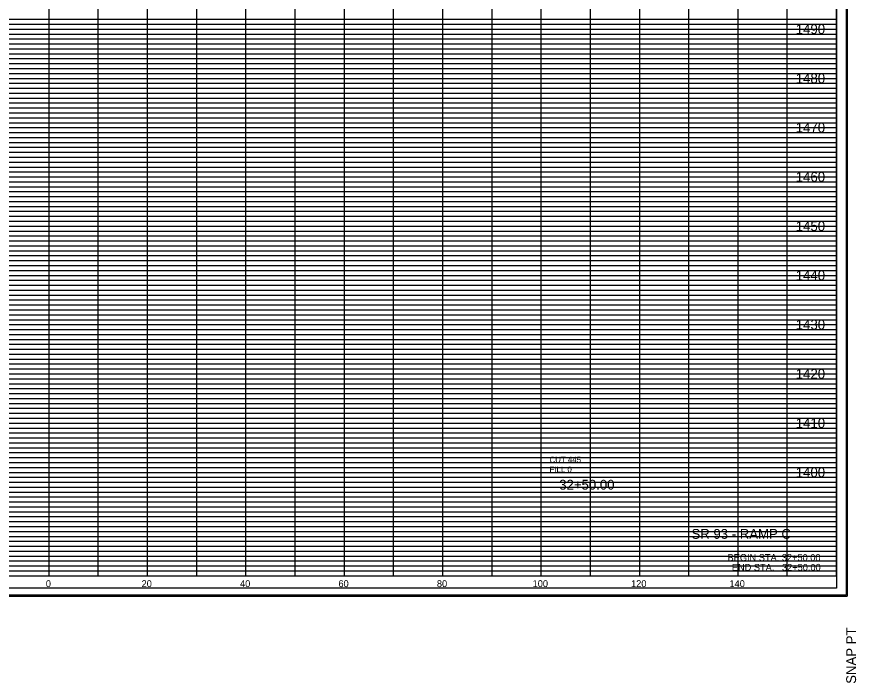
# Model space of a CAD drawing. Extents: x 980 to 2064, y 978 to 2267.
# Drawn here: x 1523.4 to 1694, y 978.2 to 1113.5 of the extents above; entities that cross this region are included whole.
import ezdxf

# ---------------------------------------------------------------- set-up
doc = ezdxf.new("R2010")
doc.units = 0
for name, color, linetype in [('Default', 7, 'Continuous'), ('DESIGN - SHEET - Corner Text', 7, 'Continuous'), ('DESIGN - SHEET - Light Grid', 7, 'Continuous'), ('DESIGN - SHEET - Linework', 7, 'Continuous'), ('DESIGN - SHEET - Plot Shape', 7, 'Continuous'), ('DESIGN - TYPICAL - Text', 7, 'Continuous')]:
    doc.layers.add(name, color=color, linetype=linetype)

# ---------------------------------------------------------------- blocks, each defined once
blk = doc.blocks.new('XSTSHT')
at = {"layer": 'DESIGN - SHEET - Light Grid'}
for p, q in [((8, 11.3), (16, 11.3)), ((16, 11.3), (24, 11.3)), ((24, 11.3), (32, 11.3)), ((8, 11.2), (16, 11.2)), ((8, 11.1), (16, 11.1)), ((16, 11.2), (24, 11.2)), ((16, 11.1), (24, 11.1)), ((24, 11.2), (32, 11.2)), ((24, 11.1), (32, 11.1)), ((8, 10.9), (16, 10.9)), ((8, 10.8), (16, 10.8)), ((16, 10.9), (24, 10.9)), ((16, 10.8), (24, 10.8)), ((24, 10.9), (32, 10.9)), ((24, 10.8), (32, 10.8)), ((8, 10.7), (16, 10.7)), ((8, 10.6), (16, 10.6)), ((16, 10.7), (24, 10.7)), ((16, 10.6), (24, 10.6)), ((24, 10.7), (32, 10.7)), ((24, 10.6), (32, 10.6)), ((8, 10.5), (16, 10.5)), ((16, 10.5), (24, 10.5)), ((24, 10.5), (32, 10.5)), ((8, 10.4), (16, 10.4)), ((8, 10.3), (16, 10.3)), ((16, 10.4), (24, 10.4)), ((16, 10.3), (24, 10.3)), ((24, 10.4), (32, 10.4)), ((24, 10.3), (32, 10.3)), ((8, 10.2), (16, 10.2)), ((8, 10.1), (16, 10.1)), ((16, 10.2), (24, 10.2)), ((16, 10.1), (24, 10.1)), ((24, 10.2), (32, 10.2)), ((24, 10.1), (32, 10.1)), ((8, 9.9), (16, 9.9)), ((16, 9.9), (24, 9.9)), ((24, 9.9), (32, 9.9)), ((8, 9.8), (16, 9.8)), ((16, 9.8), (24, 9.8)), ((24, 9.8), (32, 9.8)), ((8, 9.7), (16, 9.7)), ((8, 9.6), (16, 9.6)), ((16, 9.7), (24, 9.7)), ((16, 9.6), (24, 9.6)), ((24, 9.7), (32, 9.7)), ((24, 9.6), (32, 9.6)), ((8, 9.5), (16, 9.5)), ((8, 9.4), (16, 9.4)), ((16, 9.5), (24, 9.5)), ((16, 9.4), (24, 9.4)), ((24, 9.5), (32, 9.5)), ((24, 9.4), (32, 9.4)), ((8, 9.3), (16, 9.3)), ((16, 9.3), (24, 9.3)), ((24, 9.3), (32, 9.3)), ((8, 9.2), (16, 9.2)), ((8, 9.1), (16, 9.1)), ((16, 9.2), (24, 9.2)), ((16, 9.1), (24, 9.1)), ((24, 9.2), (32, 9.2)), ((24, 9.1), (32, 9.1)), ((8, 8.9), (16, 8.9)), ((16, 8.9), (24, 8.9)), ((24, 8.9), (32, 8.9)), ((8, 8.8), (16, 8.8)), ((8, 8.7), (16, 8.7)), ((16, 8.8), (24, 8.8)), ((16, 8.7), (24, 8.7)), ((24, 8.8), (32, 8.8)), ((24, 8.7), (32, 8.7)), ((8, 8.6), (16, 8.6)), ((16, 8.6), (24, 8.6)), ((24, 8.6), (32, 8.6)), ((8, 8.5), (16, 8.5)), ((8, 8.4), (16, 8.4)), ((16, 8.5), (24, 8.5)), ((16, 8.4), (24, 8.4)), ((24, 8.5), (32, 8.5)), ((24, 8.4), (32, 8.4)), ((8, 8.3), (16, 8.3)), ((8, 8.2), (16, 8.2)), ((16, 8.3), (24, 8.3)), ((16, 8.2), (24, 8.2)), ((24, 8.3), (32, 8.3)), ((24, 8.2), (32, 8.2)), ((8, 8.1), (16, 8.1)), ((16, 8.1), (24, 8.1)), ((24, 8.1), (32, 8.1)), ((8, 7.9), (16, 7.9)), ((16, 7.9), (24, 7.9)), ((24, 7.9), (32, 7.9)), ((8, 7.8), (16, 7.8)), ((8, 7.7), (16, 7.7)), ((16, 7.8), (24, 7.8)), ((16, 7.7), (24, 7.7)), ((24, 7.8), (32, 7.8)), ((24, 7.7), (32, 7.7)), ((8, 7.6), (16, 7.6)), ((16, 7.6), (24, 7.6)), ((24, 7.6), (32, 7.6)), ((8, 7.5), (16, 7.5)), ((8, 7.4), (16, 7.4)), ((16, 7.5), (24, 7.5)), ((16, 7.4), (24, 7.4)), ((24, 7.5), (32, 7.5)), ((24, 7.4), (32, 7.4)), ((8, 7.3), (16, 7.3)), ((8, 7.2), (16, 7.2)), ((16, 7.3), (24, 7.3)), ((16, 7.2), (24, 7.2)), ((24, 7.3), (32, 7.3)), ((24, 7.2), (32, 7.2)), ((8, 7.1), (16, 7.1)), ((16, 7.1), (24, 7.1)), ((24, 7.1), (32, 7.1)), ((8, 6.9), (16, 6.9)), ((16, 6.9), (24, 6.9)), ((24, 6.9), (32, 6.9)), ((8, 6.8), (16, 6.8)), ((8, 6.7), (16, 6.7)), ((16, 6.8), (24, 6.8)), ((16, 6.7), (24, 6.7)), ((24, 6.8), (32, 6.8)), ((24, 6.7), (32, 6.7)), ((8, 6.6), (16, 6.6)), ((8, 6.5), (16, 6.5)), ((16, 6.6), (24, 6.6)), ((16, 6.5), (24, 6.5)), ((24, 6.6), (32, 6.6)), ((24, 6.5), (32, 6.5)), ((8, 6.4), (16, 6.4)), ((16, 6.4), (24, 6.4)), ((24, 6.4), (32, 6.4)), ((8, 6.3), (16, 6.3)), ((8, 6.2), (16, 6.2)), ((16, 6.3), (24, 6.3)), ((16, 6.2), (24, 6.2)), ((24, 6.3), (32, 6.3)), ((24, 6.2), (32, 6.2)), ((8, 6.1), (16, 6.1)), ((16, 6.1), (24, 6.1)), ((24, 6.1), (32, 6.1)), ((8, 5.9), (16, 5.9)), ((8, 5.8), (16, 5.8)), ((16, 5.9), (24, 5.9)), ((16, 5.8), (24, 5.8)), ((24, 5.9), (32, 5.9)), ((24, 5.8), (32, 5.8)), ((8, 5.7), (16, 5.7)), ((16, 5.7), (24, 5.7)), ((24, 5.7), (32, 5.7)), ((8, 5.6), (16, 5.6)), ((8, 5.5), (16, 5.5)), ((16, 5.6), (24, 5.6)), ((16, 5.5), (24, 5.5)), ((24, 5.6), (32, 5.6)), ((24, 5.5), (32, 5.5)), ((8, 5.4), (16, 5.4)), ((8, 5.3), (16, 5.3)), ((16, 5.4), (24, 5.4)), ((16, 5.3), (24, 5.3)), ((24, 5.4), (32, 5.4)), ((24, 5.3), (32, 5.3)), ((8, 5.2), (16, 5.2)), ((16, 5.2), (24, 5.2)), ((24, 5.2), (32, 5.2)), ((8, 5.1), (16, 5.1)), ((16, 5.1), (24, 5.1)), ((24, 5.1), (32, 5.1)), ((8, 4.9), (16, 4.9)), ((8, 4.8), (16, 4.8)), ((16, 4.9), (24, 4.9)), ((16, 4.8), (24, 4.8)), ((24, 4.9), (32, 4.9)), ((24, 4.8), (32, 4.8)), ((8, 4.7), (16, 4.7)), ((16, 4.7), (24, 4.7)), ((24, 4.7), (32, 4.7)), ((8, 4.6), (16, 4.6)), ((8, 4.5), (16, 4.5)), ((16, 4.6), (24, 4.6)), ((16, 4.5), (24, 4.5)), ((24, 4.6), (32, 4.6)), ((24, 4.5), (32, 4.5)), ((8, 4.4), (16, 4.4)), ((8, 4.3), (16, 4.3)), ((16, 4.4), (24, 4.4)), ((16, 4.3), (24, 4.3)), ((24, 4.4), (32, 4.4)), ((24, 4.3), (32, 4.3)), ((8, 4.2), (16, 4.2)), ((8, 4.1), (16, 4.1)), ((16, 4.2), (24, 4.2)), ((16, 4.1), (24, 4.1)), ((24, 4.2), (32, 4.2)), ((24, 4.1), (32, 4.1)), ((8, 3.9), (16, 3.9)), ((8, 3.8), (16, 3.8)), ((16, 3.9), (24, 3.9)), ((16, 3.8), (24, 3.8)), ((24, 3.9), (32, 3.9)), ((24, 3.8), (32, 3.8)), ((8, 3.7), (16, 3.7)), ((8, 3.6), (16, 3.6)), ((16, 3.7), (24, 3.7)), ((16, 3.6), (24, 3.6)), ((24, 3.7), (32, 3.7)), ((24, 3.6), (32, 3.6)), ((8, 3.5), (16, 3.5)), ((16, 3.5), (24, 3.5)), ((24, 3.5), (32, 3.5)), ((8, 3.4), (16, 3.4)), ((8, 3.3), (16, 3.3)), ((16, 3.4), (24, 3.4)), ((16, 3.3), (24, 3.3)), ((24, 3.4), (32, 3.4)), ((24, 3.3), (32, 3.3)), ((8, 3.2), (16, 3.2)), ((8, 3.1), (16, 3.1)), ((16, 3.2), (24, 3.2)), ((16, 3.1), (24, 3.1)), ((24, 3.2), (32, 3.2)), ((24, 3.1), (32, 3.1)), ((8, 2.9), (16, 2.9)), ((16, 2.9), (24, 2.9)), ((24, 2.9), (32, 2.9)), ((8, 2.8), (16, 2.8)), ((16, 2.8), (24, 2.8)), ((24, 2.8), (32, 2.8)), ((8, 2.7), (16, 2.7)), ((8, 2.6), (16, 2.6)), ((16, 2.7), (24, 2.7)), ((16, 2.6), (24, 2.6)), ((24, 2.7), (32, 2.7)), ((24, 2.6), (32, 2.6)), ((8, 2.5), (16, 2.5)), ((8, 2.4), (16, 2.4)), ((16, 2.5), (24, 2.5)), ((16, 2.4), (24, 2.4)), ((24, 2.5), (32, 2.5)), ((24, 2.4), (32, 2.4)), ((8, 2.3), (16, 2.3)), ((16, 2.3), (24, 2.3)), ((24, 2.3), (32, 2.3)), ((8, 2.2), (16, 2.2)), ((8, 2.1), (16, 2.1)), ((16, 2.2), (24, 2.2)), ((16, 2.1), (24, 2.1)), ((24, 2.2), (32, 2.2)), ((24, 2.1), (32, 2.1)), ((8, 1.9), (16, 1.9)), ((16, 1.9), (24, 1.9)), ((24, 1.9), (32, 1.9)), ((8, 1.8), (16, 1.8)), ((16, 1.8), (24, 1.8)), ((24, 1.8), (32, 1.8)), ((8, 1.7), (16, 1.7)), ((8, 1.6), (16, 1.6)), ((16, 1.7), (24, 1.7)), ((16, 1.6), (24, 1.6)), ((24, 1.7), (32, 1.7)), ((24, 1.6), (32, 1.6)), ((8, 1.5), (16, 1.5)), ((8, 1.4), (16, 1.4)), ((16, 1.5), (24, 1.5)), ((16, 1.4), (24, 1.4)), ((24, 1.5), (32, 1.5)), ((24, 1.4), (32, 1.4)), ((8, 1.3), (16, 1.3)), ((8, 1.2), (16, 1.2)), ((16, 1.3), (24, 1.3)), ((16, 1.2), (24, 1.2)), ((24, 1.3), (32, 1.3)), ((24, 1.2), (32, 1.2)), ((8, 1.1), (16, 1.1)), ((16, 1.1), (24, 1.1)), ((24, 1.1), (32, 1.1)), ((8, 0.9), (16, 0.9)), ((16, 0.9), (24, 0.9)), ((24, 0.9), (32, 0.9)), ((8, 0.8), (16, 0.8)), ((8, 0.7), (16, 0.7)), ((16, 0.8), (24, 0.8)), ((16, 0.7), (24, 0.7)), ((24, 0.8), (32, 0.8)), ((24, 0.7), (32, 0.7)), ((8, 0.6), (16, 0.6)), ((16, 0.6), (24, 0.6)), ((24, 0.6), (32, 0.6)), ((8, 0.5), (16, 0.5)), ((8, 0.4), (16, 0.4)), ((16, 0.5), (24, 0.5)), ((16, 0.4), (24, 0.4)), ((24, 0.5), (32, 0.5)), ((24, 0.4), (32, 0.4)), ((8, 0.3), (16, 0.3)), ((8, 0.2), (16, 0.2)), ((16, 0.3), (24, 0.3)), ((16, 0.2), (24, 0.2)), ((24, 0.3), (32, 0.3)), ((24, 0.2), (32, 0.2)), ((8, 0.1), (16, 0.1)), ((16, 0.1), (24, 0.1)), ((24, 0.1), (32, 0.1))]:
    blk.add_line(p, q, dxfattribs=at)
at = {"layer": 'DESIGN - SHEET - Linework'}
for p, q in [((32.217, 21.414), (32.217, -0.414)), ((16, 0), (16, 21)), ((17, 0), (17, 21)), ((18, 0), (18, 21)), ((19, 0), (19, 21)), ((20, 0), (20, 21)), ((21, 0), (21, 21)), ((22, 0), (22, 21)), ((23, 0), (23, 21)), ((24, 0), (24, 21)), ((25, 0), (25, 21)), ((26, 0), (26, 21)), ((27, 0), (27, 21)), ((28, 0), (28, 20)), ((29, 0), (29, 20)), ((30, 0), (30, 20)), ((31, 0), (31, 20)), ((0, 11), (32, 11)), ((0, 10), (32, 10)), ((0, 9), (32, 9)), ((0, 8), (32, 8)), ((0, 7), (32, 7)), ((0, 6), (32, 6)), ((0, 5), (32, 5)), ((0, 4), (32, 4)), ((0, 3), (32, 3)), ((0, 2), (32, 2)), ((0, 1), (32, 1)), ((-1.823, -0.414), (32.217, -0.414))]:
    blk.add_line(p, q, dxfattribs=at)
blk.add_lwpolyline([(0, 21), (0, 0), (32, 0), (32, 21), (0, 21)], dxfattribs=at)
at = {"layer": 'DESIGN - SHEET - Plot Shape'}
for points in [[(-1.803, 21.394), (32.197, 21.394), (32.197, -0.394), (-1.803, -0.394)], [(-0.85, 21), (32, 21), (32, -0.25), (-0.85, -0.25)]]:
    blk.add_lwpolyline(points, close=True, dxfattribs=at)
at = {"layer": 'DESIGN - SHEET - Corner Text'}
blk.add_text('SNAP PT  ', height=0.2, rotation=90, dxfattribs=at).set_placement((32.397, -2.194))

msp = doc.modelspace()

# ---------------------------------------------------------------- block references
at = {"layer": 'Default', "xscale": 10, "yscale": 10}
msp.add_blockref('XSTSHT', (1370, 1000), dxfattribs=at)

# ---------------------------------------------------------------- texts
at = {"layer": 'Default'}
for s, height, p in [('     1490     ', 2, (1678.01, 1110)), ('     1480     ', 2, (1678.01, 1100)), ('     1470     ', 2, (1678.01, 1090)), ('     1460     ', 2, (1678.01, 1080)), ('     1450     ', 2, (1678.01, 1070)), ('     1440     ', 2, (1678.01, 1060)), ('     1430     ', 2, (1678.01, 1050)), ('     1420     ', 2, (1678.01, 1040)), ('     1410     ', 2, (1678.01, 1030)), ('     1400     ', 2, (1678.01, 1020)), ('     32+50.00     ', 2, (1629.94, 1017.49)), ('     0     ', 1.4, (1526.74, 997.7)), ('     0     ', 1.4, (1526.74, 997.7)), ('     20     ', 1.4, (1546.2, 997.7)), ('     40     ', 1.4, (1566.2, 997.7)), ('     60     ', 1.4, (1586.2, 997.7)), ('     80     ', 1.4, (1606.2, 997.7)), ('     100     ', 1.4, (1625.65, 997.7)), ('     120     ', 1.4, (1645.65, 997.7)), ('     140     ', 1.4, (1665.65, 997.7))]:
    msp.add_text(s, height=height, dxfattribs=at).set_placement(p)
at = {"layer": 'DESIGN - SHEET - Corner Text'}
for s, height, p in [('SR 93 - RAMP C', 2, (1660.53, 1007.5)), ('BEGIN STA. 32+50.00', 1.4, (1667.86, 1003)), ('END STA.   32+50.00', 1.4, (1668.73, 1001))]:
    msp.add_text(s, height=height, dxfattribs=at).set_placement(p)
at = {"layer": 'DESIGN - TYPICAL - Text'}
for s, p in [('CUT 445', (1631.67, 1022.97)), ('FILL 0', (1631.67, 1020.97))]:
    msp.add_text(s, height=1.2, dxfattribs=at).set_placement(p)

doc.saveas('drawing.dxf')
